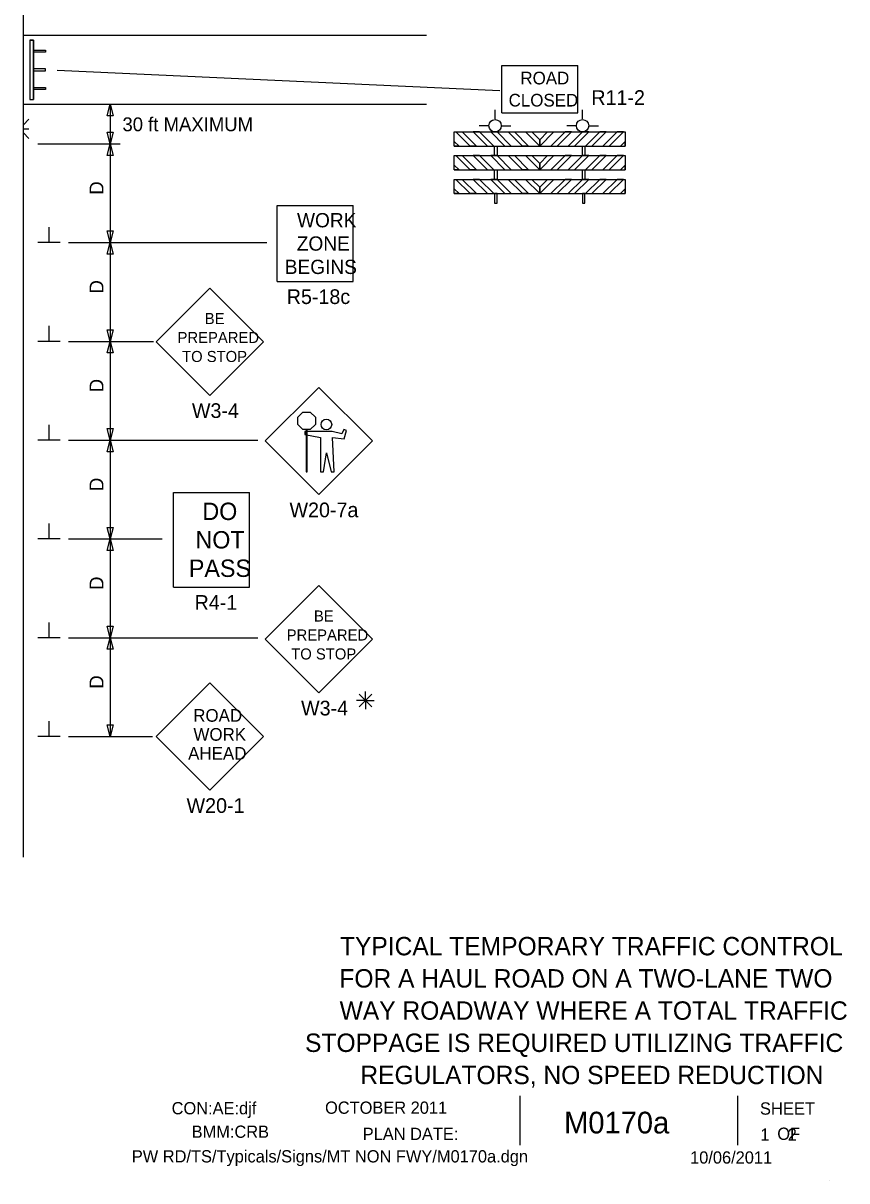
# Model space of a CAD drawing. Extents: x 16735 to 18477, y 4638 to 5631.
# Drawn here: x 17016 to 17432, y 4638 to 5224 of the extents above; entities that cross this region are included whole.
import ezdxf

# ---------------------------------------------------------------- set-up
doc = ezdxf.new("R2010")
doc.units = 0
for name, color, linetype in [('BORDER', 7, 'Continuous'), ('BORDER_SIGNAL_WO', 7, 'Continuous'), ('PAVT_EDGE_EX', 7, 'Continuous'), ('TRAFFIC_SIGNS_PR', 7, 'Continuous'), ('TYPICAL_TEXT_DIMEN_PR', 7, 'Continuous')]:
    doc.layers.add(name, color=color, linetype=linetype)

msp = doc.modelspace()

# ---------------------------------------------------------------- linework, layer by layer
at = {"layer": 'BORDER'}
for p, q in [((17266.99, 4656.25), (17266.99, 4681.25)), ((17377.05, 4656.25), (17377.05, 4681.25)), ((17423.55, 4638.15), (17423.55, 4638.15))]:
    msp.add_line(p, q, dxfattribs=at)
at = {"layer": 'PAVT_EDGE_EX'}
for p, q in [((17015.59, 5623.96), (17015.59, 4802.04)), ((17015.59, 5217.98), (17219.58, 5217.98)), ((17015.59, 5183), (17219.58, 5183))]:
    msp.add_line(p, q, dxfattribs=at)
at = {"layer": 'TRAFFIC_SIGNS_PR'}
for p, q in [((17018.89, 5215.39), (17018.89, 5185.39)), ((17018.89, 5215.39), (17020.89, 5215.39)), ((17020.89, 5215.39), (17020.89, 5185.39)), ((17257.68, 5178.65), (17257.68, 5202.65)), ((17257.68, 5202.65), (17296.08, 5202.65)), ((17296.08, 5178.65), (17296.08, 5202.65)), ((17018.89, 5185.39), (17020.89, 5185.39)), ((17254.28, 5175.69), (17254.28, 5180.19)), ((17298.55, 5175.69), (17298.55, 5180.19)), ((17018.53, 5175.4), (17015.71, 5172.58)), ((17257.68, 5178.65), (17296.08, 5178.65)), ((17015.71, 5170.55), (17018.53, 5170.55)), ((17018.53, 5165.7), (17015.71, 5168.52)), ((17233.68, 5168.98), (17320.08, 5168.98)), ((17233.68, 5161.78), (17233.68, 5168.98)), ((17241.68, 5161.78), (17234.48, 5168.98)), ((17244.88, 5161.78), (17237.68, 5168.98)), ((17250.48, 5161.78), (17243.28, 5168.98)), ((17250.73, 5172.14), (17246.3, 5172.14)), ((17253.68, 5161.78), (17246.48, 5168.98)), ((17259.28, 5161.78), (17252.08, 5168.98)), ((17262.48, 5161.78), (17255.28, 5168.98)), ((17257.83, 5172.14), (17262.31, 5172.14)), ((17268.08, 5161.78), (17260.88, 5168.98)), ((17271.28, 5161.78), (17264.08, 5168.98)), ((17276.88, 5161.78), (17269.68, 5168.98)), ((17276.88, 5164.98), (17272.88, 5168.98)), ((17276.88, 5161.78), (17284.08, 5168.98)), ((17276.88, 5164.98), (17280.88, 5168.98)), ((17282.48, 5161.78), (17289.68, 5168.98)), ((17285.68, 5161.78), (17292.88, 5168.98)), ((17295, 5172.14), (17290.57, 5172.14)), ((17291.28, 5161.78), (17298.48, 5168.98)), ((17294.48, 5161.78), (17301.68, 5168.98)), ((17300.08, 5161.78), (17307.28, 5168.98)), ((17302.1, 5172.14), (17306.58, 5172.14)), ((17303.28, 5161.78), (17310.48, 5168.98)), ((17308.88, 5161.78), (17316.08, 5168.98)), ((17312.08, 5161.78), (17319.28, 5168.98)), ((17320.08, 5168.98), (17320.08, 5161.78)), ((17236.08, 5161.78), (17233.68, 5164.18)), ((17233.68, 5161.78), (17320.08, 5161.78)), ((17317.68, 5161.78), (17320.08, 5164.18)), ((17233.68, 5156.98), (17320.08, 5156.98)), ((17233.68, 5149.78), (17233.68, 5156.98)), ((17241.68, 5149.78), (17234.48, 5156.98)), ((17244.88, 5149.78), (17237.68, 5156.98)), ((17250.48, 5149.78), (17243.28, 5156.98)), ((17253.68, 5149.78), (17246.48, 5156.98)), ((17259.28, 5149.78), (17252.08, 5156.98)), ((17262.48, 5149.78), (17255.28, 5156.98)), ((17268.08, 5149.78), (17260.88, 5156.98)), ((17271.28, 5149.78), (17264.08, 5156.98)), ((17276.88, 5149.78), (17269.68, 5156.98)), ((17276.88, 5152.98), (17272.88, 5156.98)), ((17276.88, 5149.78), (17284.08, 5156.98)), ((17276.88, 5152.98), (17280.88, 5156.98)), ((17282.48, 5149.78), (17289.68, 5156.98)), ((17285.68, 5149.78), (17292.88, 5156.98)), ((17291.28, 5149.78), (17298.48, 5156.98)), ((17294.48, 5149.78), (17301.68, 5156.98)), ((17300.08, 5149.78), (17307.28, 5156.98)), ((17303.28, 5149.78), (17310.48, 5156.98)), ((17308.88, 5149.78), (17316.08, 5156.98)), ((17312.08, 5149.78), (17319.28, 5156.98)), ((17320.08, 5156.98), (17320.08, 5149.78)), ((17236.08, 5149.78), (17233.68, 5152.18)), ((17317.68, 5149.78), (17320.08, 5152.18)), ((17233.68, 5149.78), (17320.08, 5149.78)), ((17233.68, 5144.98), (17320.08, 5144.98)), ((17233.68, 5137.78), (17233.68, 5144.98)), ((17241.68, 5137.78), (17234.48, 5144.98)), ((17244.88, 5137.78), (17237.68, 5144.98)), ((17250.48, 5137.78), (17243.28, 5144.98)), ((17253.68, 5137.78), (17246.48, 5144.98)), ((17259.28, 5137.78), (17252.08, 5144.98)), ((17262.48, 5137.78), (17255.28, 5144.98)), ((17268.08, 5137.78), (17260.88, 5144.98)), ((17271.28, 5137.78), (17264.08, 5144.98)), ((17276.88, 5137.78), (17269.68, 5144.98)), ((17276.88, 5140.98), (17272.88, 5144.98)), ((17276.88, 5137.78), (17284.08, 5144.98)), ((17276.88, 5140.98), (17280.88, 5144.98)), ((17282.48, 5137.78), (17289.68, 5144.98)), ((17285.68, 5137.78), (17292.88, 5144.98)), ((17291.28, 5137.78), (17298.48, 5144.98)), ((17294.48, 5137.78), (17301.68, 5144.98)), ((17300.08, 5137.78), (17307.28, 5144.98)), ((17303.28, 5137.78), (17310.48, 5144.98)), ((17308.88, 5137.78), (17316.08, 5144.98)), ((17312.08, 5137.78), (17319.28, 5144.98)), ((17320.08, 5144.98), (17320.08, 5137.78)), ((17236.08, 5137.78), (17233.68, 5140.18)), ((17317.68, 5137.78), (17320.08, 5140.18)), ((17233.68, 5137.78), (17320.08, 5137.78)), ((17144.11, 5093.34), (17144.11, 5131.74)), ((17144.11, 5131.74), (17182.51, 5131.74)), ((17182.51, 5093.34), (17182.51, 5131.74)), ((17144.11, 5093.34), (17182.51, 5093.34)), ((17109.95, 5089.97), (17082.79, 5062.82)), ((17137.1, 5062.82), (17109.95, 5089.97)), ((17082.79, 5062.82), (17109.95, 5035.67)), ((17109.95, 5035.67), (17137.1, 5062.82)), ((17165.17, 5039.73), (17138.02, 5012.58)), ((17192.32, 5012.58), (17165.17, 5039.73)), ((17138.02, 5012.58), (17165.17, 4985.42)), ((17165.17, 4985.42), (17192.32, 5012.58)), ((17091.62, 4938.58), (17091.62, 4986.58)), ((17091.62, 4986.58), (17130.02, 4986.58)), ((17130.02, 4938.58), (17130.02, 4986.58)), ((17165.16, 4939.42), (17138.01, 4912.27)), ((17192.31, 4912.27), (17165.16, 4939.42)), ((17091.62, 4938.58), (17130.02, 4938.58)), ((17138.01, 4912.27), (17165.16, 4885.12)), ((17165.16, 4885.12), (17192.31, 4912.27)), ((17110.07, 4890.11), (17082.91, 4862.95)), ((17137.22, 4862.95), (17110.07, 4890.11)), ((17082.91, 4862.95), (17110.07, 4835.8)), ((17110.07, 4835.8), (17137.22, 4862.95))]:
    msp.add_line(p, q, dxfattribs=at)
for points in [[(17018.89, 5215.39), (17018.89, 5185.39), (17020.89, 5185.39), (17020.89, 5215.39)], [(17020.89, 5210.39), (17026.89, 5210.39), (17026.89, 5209.39), (17020.89, 5209.39)], [(17020.89, 5200.89), (17020.89, 5199.89), (17026.89, 5199.89), (17026.89, 5200.89)], [(17026.89, 5191.39), (17026.89, 5190.39), (17020.89, 5190.39), (17020.89, 5191.39)], [(17244.88, 5161.78), (17241.68, 5161.78), (17234.48, 5168.98), (17237.68, 5168.98)], [(17253.68, 5161.78), (17246.48, 5168.98), (17243.28, 5168.98), (17250.48, 5161.78)], [(17262.48, 5161.78), (17255.28, 5168.98), (17252.08, 5168.98), (17259.28, 5161.78)], [(17271.28, 5161.78), (17268.08, 5161.78), (17260.88, 5168.98), (17264.08, 5168.98)], [(17276.88, 5161.78), (17269.68, 5168.98), (17272.88, 5168.98), (17276.88, 5164.98)], [(17276.88, 5161.78), (17276.88, 5164.98), (17280.88, 5168.98), (17284.08, 5168.98)], [(17282.48, 5161.78), (17285.68, 5161.78), (17292.88, 5168.98), (17289.68, 5168.98)], [(17291.28, 5161.78), (17294.48, 5161.78), (17301.68, 5168.98), (17298.48, 5168.98)], [(17300.08, 5161.78), (17303.28, 5161.78), (17310.48, 5168.98), (17307.28, 5168.98)], [(17308.88, 5161.78), (17312.08, 5161.78), (17319.28, 5168.98), (17316.08, 5168.98)], [(17236.08, 5161.78), (17233.68, 5161.78), (17233.68, 5164.18)], [(17254.08, 5156.98), (17254.08, 5161.78), (17255.28, 5161.78), (17255.28, 5156.98)], [(17298.48, 5156.98), (17298.48, 5161.78), (17299.68, 5161.78), (17299.68, 5156.98)], [(17317.68, 5161.78), (17320.08, 5161.78), (17320.08, 5164.18)], [(17244.88, 5149.78), (17241.68, 5149.78), (17234.48, 5156.98), (17237.68, 5156.98)], [(17253.68, 5149.78), (17246.48, 5156.98), (17243.28, 5156.98), (17250.48, 5149.78)], [(17262.48, 5149.78), (17255.28, 5156.98), (17252.08, 5156.98), (17259.28, 5149.78)], [(17271.28, 5149.78), (17268.08, 5149.78), (17260.88, 5156.98), (17264.08, 5156.98)], [(17276.88, 5149.78), (17269.68, 5156.98), (17272.88, 5156.98), (17276.88, 5152.98)], [(17276.88, 5149.78), (17276.88, 5152.98), (17280.88, 5156.98), (17284.08, 5156.98)], [(17282.48, 5149.78), (17285.68, 5149.78), (17292.88, 5156.98), (17289.68, 5156.98)], [(17291.28, 5149.78), (17294.48, 5149.78), (17301.68, 5156.98), (17298.48, 5156.98)], [(17300.08, 5149.78), (17303.28, 5149.78), (17310.48, 5156.98), (17307.28, 5156.98)], [(17308.88, 5149.78), (17312.08, 5149.78), (17319.28, 5156.98), (17316.08, 5156.98)], [(17236.08, 5149.78), (17233.68, 5149.78), (17233.68, 5152.18)], [(17317.68, 5149.78), (17320.08, 5149.78), (17320.08, 5152.18)], [(17244.88, 5137.78), (17241.68, 5137.78), (17234.48, 5144.98), (17237.68, 5144.98)], [(17253.68, 5137.78), (17246.48, 5144.98), (17243.28, 5144.98), (17250.48, 5137.78)], [(17262.48, 5137.78), (17255.28, 5144.98), (17252.08, 5144.98), (17259.28, 5137.78)], [(17254.08, 5144.98), (17254.08, 5149.78), (17255.28, 5149.78), (17255.28, 5144.98)], [(17271.28, 5137.78), (17268.08, 5137.78), (17260.88, 5144.98), (17264.08, 5144.98)], [(17276.88, 5137.78), (17269.68, 5144.98), (17272.88, 5144.98), (17276.88, 5140.98)], [(17276.88, 5137.78), (17276.88, 5140.98), (17280.88, 5144.98), (17284.08, 5144.98)], [(17282.48, 5137.78), (17285.68, 5137.78), (17292.88, 5144.98), (17289.68, 5144.98)], [(17291.28, 5137.78), (17294.48, 5137.78), (17301.68, 5144.98), (17298.48, 5144.98)], [(17298.48, 5144.98), (17298.48, 5149.78), (17299.68, 5149.78), (17299.68, 5144.98)], [(17300.08, 5137.78), (17303.28, 5137.78), (17310.48, 5144.98), (17307.28, 5144.98)], [(17308.88, 5137.78), (17312.08, 5137.78), (17319.28, 5144.98), (17316.08, 5144.98)], [(17236.08, 5137.78), (17233.68, 5137.78), (17233.68, 5140.18)], [(17317.68, 5137.78), (17320.08, 5137.78), (17320.08, 5140.18)], [(17254.08, 5137.81), (17254.08, 5133.01), (17255.28, 5133.01), (17255.28, 5137.81)], [(17298.48, 5137.81), (17298.48, 5133.01), (17299.68, 5133.01), (17299.68, 5137.81)], [(17157.13, 5027.21), (17160.81, 5027.21), (17163.4, 5024.61), (17163.4, 5020.94), (17160.81, 5018.34), (17157.13, 5018.34), (17154.53, 5020.94), (17154.53, 5024.61)], [(17171.85, 5017.3), (17158.03, 5017.3), (17158.03, 5015.8), (17165.99, 5014.34), (17165.99, 4996.94), (17167.49, 4996.94), (17168.99, 5006.54), (17171.4, 4996.94), (17172.9, 4996.94), (17171.99, 5014.34), (17177.99, 5013.74), (17179.19, 5017.94), (17177.74, 5018.31), (17176.84, 5016.21)], [(17158.67, 5018.34), (17158.67, 4996.96), (17159.26, 4996.96), (17159.26, 5018.34)]]:
    msp.add_lwpolyline(points, close=True, dxfattribs=at)
for centre, radius in [((17254.28, 5172.14), 3.13), ((17298.55, 5172.14), 3.13), ((17168.97, 5020.91), 2.7)]:
    msp.add_circle(centre, radius, dxfattribs=at)
at = {"layer": 'TYPICAL_TEXT_DIMEN_PR'}
for p, q in [((17018.89, 5217.98), (17064.59, 5217.98)), ((17032.74, 5200.22), (17256.76, 5189.9)), ((17018.89, 5183), (17064.59, 5183)), ((17058.02, 5177.14), (17059.59, 5183)), ((17059.59, 5183), (17061.16, 5177.14)), ((17059.59, 5183), (17059.59, 5163)), ((17059.59, 5177.14), (17058.02, 5177.14)), ((17061.16, 5177.14), (17059.59, 5177.14)), ((17059.59, 5163), (17058.02, 5168.86)), ((17058.02, 5168.86), (17059.59, 5168.86)), ((17059.59, 5168.86), (17061.16, 5168.86)), ((17061.16, 5168.86), (17059.59, 5163)), ((17023.07, 5163), (17064.59, 5163)), ((17058.02, 5157.14), (17059.59, 5163)), ((17059.59, 5163), (17059.59, 5113)), ((17059.59, 5163), (17061.16, 5157.14)), ((17059.59, 5157.14), (17058.02, 5157.14)), ((17061.16, 5157.14), (17059.59, 5157.14)), ((17028.72, 5113), (17028.72, 5120.79)), ((17059.59, 5113), (17058.02, 5118.86)), ((17058.02, 5118.86), (17059.59, 5118.86)), ((17059.59, 5118.86), (17061.16, 5118.86)), ((17061.16, 5118.86), (17059.59, 5113)), ((17034.34, 5113), (17023.09, 5113)), ((17038.59, 5113), (17138.86, 5113)), ((17058.02, 5107.14), (17059.59, 5113)), ((17058.02, 5107.14), (17059.59, 5113)), ((17059.59, 5113), (17061.16, 5107.14)), ((17059.59, 5113), (17061.16, 5107.14)), ((17059.59, 5113), (17059.59, 5063)), ((17059.59, 5107.14), (17058.02, 5107.14)), ((17059.59, 5107.14), (17058.02, 5107.14)), ((17061.16, 5107.14), (17059.59, 5107.14)), ((17061.16, 5107.14), (17059.59, 5107.14)), ((17028.72, 5063), (17028.72, 5070.79)), ((17059.59, 5063), (17058.02, 5068.86)), ((17058.02, 5068.86), (17059.59, 5068.86)), ((17059.59, 5068.86), (17061.16, 5068.86)), ((17061.16, 5068.86), (17059.59, 5063)), ((17034.34, 5063), (17023.09, 5063)), ((17038.59, 5063), (17081.48, 5063)), ((17058.02, 5057.14), (17059.59, 5063)), ((17058.02, 5057.14), (17059.59, 5063)), ((17059.59, 5063), (17059.59, 5013)), ((17059.59, 5063), (17061.16, 5057.14)), ((17059.59, 5063), (17061.16, 5057.14)), ((17059.59, 5057.14), (17058.02, 5057.14)), ((17059.59, 5057.14), (17058.02, 5057.14)), ((17061.16, 5057.14), (17059.59, 5057.14)), ((17061.16, 5057.14), (17059.59, 5057.14)), ((17028.72, 5013), (17028.72, 5020.79)), ((17059.59, 5013), (17058.02, 5018.86)), ((17058.02, 5018.86), (17059.59, 5018.86)), ((17059.59, 5018.86), (17061.16, 5018.86)), ((17061.16, 5018.86), (17059.59, 5013)), ((17034.34, 5013), (17023.09, 5013)), ((17038.59, 5013), (17134.3, 5013)), ((17058.02, 5007.14), (17059.59, 5013)), ((17059.59, 5013), (17059.59, 4963)), ((17059.59, 5013), (17061.16, 5007.14)), ((17059.59, 5007.14), (17058.02, 5007.14)), ((17061.16, 5007.14), (17059.59, 5007.14)), ((17028.72, 4963), (17028.72, 4970.79)), ((17059.59, 4963), (17058.02, 4968.86)), ((17058.02, 4968.86), (17059.59, 4968.86)), ((17059.59, 4968.86), (17061.16, 4968.86)), ((17061.16, 4968.86), (17059.59, 4963)), ((17034.34, 4963), (17023.09, 4963)), ((17038.59, 4963), (17085.87, 4963)), ((17058.02, 4957.14), (17059.59, 4963)), ((17059.59, 4963), (17059.59, 4913)), ((17059.59, 4963), (17061.16, 4957.14)), ((17059.59, 4957.14), (17058.02, 4957.14)), ((17061.16, 4957.14), (17059.59, 4957.14)), ((17028.72, 4913), (17028.72, 4920.79)), ((17059.59, 4913), (17058.02, 4918.86)), ((17058.02, 4918.86), (17059.59, 4918.86)), ((17059.59, 4918.86), (17061.16, 4918.86)), ((17061.16, 4918.86), (17059.59, 4913)), ((17034.34, 4913), (17023.09, 4913)), ((17038.59, 4913), (17134.3, 4913)), ((17058.02, 4907.14), (17059.59, 4913)), ((17059.59, 4913), (17059.59, 4863)), ((17059.59, 4913), (17061.16, 4907.14)), ((17059.59, 4907.14), (17058.02, 4907.14)), ((17061.16, 4907.14), (17059.59, 4907.14)), ((17188.7, 4881.28), (17184.17, 4881.28)), ((17185.51, 4884.47), (17191.89, 4878.09)), ((17191.89, 4884.47), (17185.51, 4878.09)), ((17188.7, 4881.28), (17188.7, 4885.74)), ((17188.7, 4881.28), (17191.89, 4881.28)), ((17188.7, 4881.28), (17193.18, 4881.28)), ((17188.7, 4881.28), (17188.7, 4876.78)), ((17028.72, 4863), (17028.72, 4870.79)), ((17059.59, 4863), (17058.02, 4868.86)), ((17058.02, 4868.86), (17059.59, 4868.86)), ((17059.59, 4868.86), (17061.16, 4868.86)), ((17061.16, 4868.86), (17059.59, 4863)), ((17034.34, 4863), (17023.09, 4863)), ((17038.59, 4863), (17080.95, 4863))]:
    msp.add_line(p, q, dxfattribs=at)

# ---------------------------------------------------------------- texts
at = {"layer": 'BORDER'}
for s, height, p in [('TYPICAL TEMPORARY TRAFFIC CONTROL', 9.3, (17175.83, 4752.28)), ('FOR A HAUL ROAD ON A TWO-LANE TWO', 9.3, (17175.52, 4735.98)), ('WAY ROADWAY WHERE A TOTAL TRAFFIC', 9.3, (17175.66, 4719.68)), ('STOPPAGE IS REQUIRED UTILIZING TRAFFIC', 9.3, (17158.16, 4703.38)), ('REGULATORS, NO SPEED REDUCTION', 9.3, (17186.16, 4687.08)), ('SHEET', 6.25, (17388.25, 4671.63)), ('PLAN DATE:', 6.2, (17187.35, 4658.82)), ('OF', 6.2, (17397.04, 4658.89))]:
    msp.add_text(s, height=height, dxfattribs=at).set_placement(p)
at = {"layer": 'BORDER_SIGNAL_WO'}
for s, height, p in [('CON:AE:djf', 6.2, (17090.69, 4671.81)), ('    OCTOBER 2011    ', 6.2, (17159.08, 4672.09)), ('    M0170a   ', 11, (17272.86, 4662.13)), ('BMM:CRB   ', 6.2, (17100.81, 4659.92)), (' 1    2 ', 6.2, (17386.18, 4658.45)), ('PW RD/TS/Typicals/Signs/MT NON FWY/M0170a.dgn    ', 6.2, (17070.55, 4647.46)), ('10/06/2011    ', 6.2, (17352.93, 4646.88))]:
    msp.add_text(s, height=height, dxfattribs=at).set_placement(p)
at = {"layer": 'TRAFFIC_SIGNS_PR'}
for s, height, p in [('ROAD', 6.4, (17267.11, 5193.05)), ('CLOSED', 6.4, (17261.15, 5181.85)), ('R11-2', 7.44, (17302.99, 5182.66)), ('WORK', 7.217, (17154.11, 5120.71)), ('ZONE', 7.217, (17153.99, 5108.9)), ('BEGINS', 7.217, (17147.92, 5097.09)), ('R5-18c', 7.44, (17148.92, 5081.9)), ('BE', 5.6, (17107.45, 5071.75)), ('PREPARED', 5.6, (17093.69, 5062.15)), ('TO STOP', 5.6, (17095.97, 5052.55)), ('W3-4', 7.44, (17100.95, 5024.23)), ('DO', 8.8, (17106.25, 4972.58)), ('W20-7a', 7.44, (17150.31, 4973.98)), ('NOT', 8.8, (17102.76, 4958.18)), ('PASS', 8.8, (17099.42, 4943.78)), ('R4-1', 7.44, (17102.3, 4927.14)), ('BE', 5.6, (17162.66, 4921.2)), ('PREPARED', 5.6, (17148.9, 4911.6)), ('TO STOP', 5.6, (17151.18, 4902)), ('W3-4', 7.44, (17156.16, 4873.68)), ('ROAD', 6.4, (17101.61, 4870.49)), ('WORK', 6.4, (17101.72, 4860.89)), ('AHEAD', 6.4, (17099.03, 4851.29)), ('W20-1', 7.44, (17098.24, 4824.36))]:
    msp.add_text(s, height=height, dxfattribs=at).set_placement(p)
at = {"layer": 'TYPICAL_TEXT_DIMEN_PR'}
msp.add_text('30 ft MAXIMUM', height=7, dxfattribs=at).set_placement((17065.81, 5169.34))
for p in [(17056.2, 5137.22), (17056.2, 5087.22), (17056.2, 5037.22), (17056.2, 4987.22), (17056.2, 4937.22), (17056.2, 4887.22)]:
    msp.add_text('D', height=7, rotation=90, dxfattribs=at).set_placement(p)

doc.saveas('drawing.dxf')
